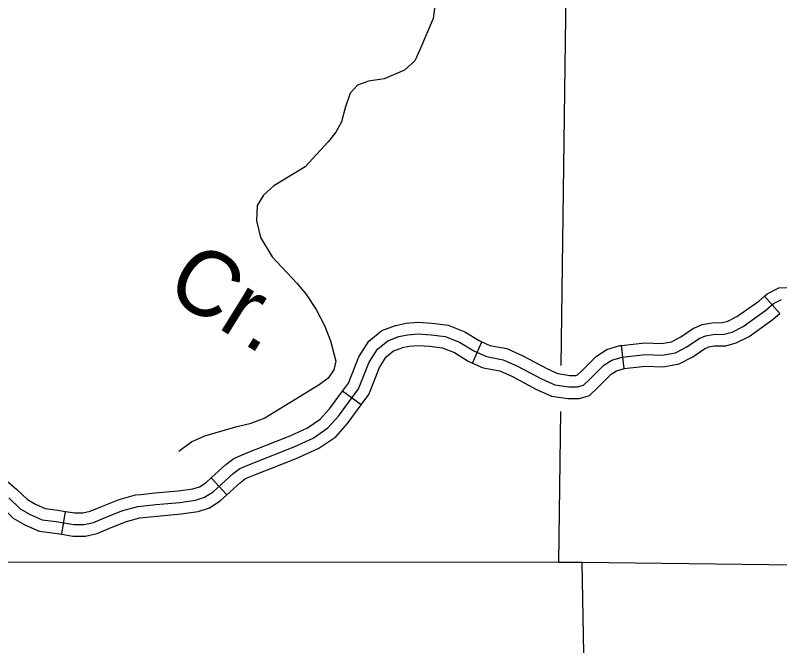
# Model space of a CAD drawing. Extents: x -19 to 366, y -4 to 359.
# Drawn here: x 136.698 to 137.635, y 197.944 to 198.716 of the extents above; entities that cross this region are included whole.
import ezdxf

# ---------------------------------------------------------------- set-up
doc = ezdxf.new("R2010")
doc.units = 0
for name, color, linetype in [('R_Axis', 7, 'Continuous'), ('R_Axis Annot', 7, 'Continuous'), ('R_Temp Easement', 7, 'Continuous'), ('Sheet Fence', 7, 'Continuous'), ('T_Indications', 7, 'Continuous')]:
    doc.layers.add(name, color=color, linetype=linetype)

msp = doc.modelspace()

# ---------------------------------------------------------------- linework, layer by layer
at = {"layer": 'R_Axis'}
msp.add_lwpolyline([(139.23142, 198.03736), (138.38944, 198.03328), (138.3734, 198.03349), (137.39231, 198.04601), (137.36365, 198.04602), (136.38943, 198.0464), (136.3709, 198.0464), (135.39084, 198.04643), (135.3637, 198.04701), (134.46147, 198.06627), (134.41844, 198.06697), (133.46736, 198.08257)], dxfattribs=at)
at = {"layer": 'R_Axis Annot'}
for points in [[(137.36682, 198.28741), (137.37684, 199.05047)], [(137.36365, 198.04602), (137.36607, 198.23073)], [(137.40599, 197.31164), (137.39231, 198.04601)]]:
    msp.add_lwpolyline(points, dxfattribs=at)
at = {"layer": 'R_Temp Easement'}
for points in [[(137.21218, 198.73082), (137.20961, 198.7126), (137.19351, 198.67384), (137.18714, 198.66054), (137.17471, 198.64911), (137.1498, 198.63839), (137.13053, 198.63566), (137.11694, 198.63068), (137.10791, 198.62078), (137.10193, 198.60293), (137.09747, 198.58584), (137.09033, 198.57329), (137.08093, 198.56112), (137.0527, 198.53066), (137.01461, 198.50737), (137.0018, 198.49594), (136.99392, 198.48339), (136.99324, 198.46442), (136.99824, 198.44395), (137.01233, 198.42049), (137.04272, 198.38798), (137.04854, 198.38124)], [(137.04854, 198.38124), (137.05375, 198.37521), (137.06631, 198.35591), (137.0766, 198.33623), (137.08386, 198.31729), (137.0904, 198.29265), (137.08817, 198.28202), (137.08103, 198.27175), (137.0701, 198.26336), (137.00334, 198.22289), (136.98523, 198.21562), (136.96747, 198.21175), (136.92933, 198.20061), (136.91385, 198.19372), (136.89802, 198.1819)]]:
    msp.add_lwpolyline(points, dxfattribs=at)
at = {"layer": 'Sheet Fence'}
for points in [[(139.44064, 1.53154), (139.25106, 10.14733), (139.06082, 18.76327), (138.86992, 27.37935), (138.67836, 35.99557), (138.48613, 44.61194), (138.29325, 53.22845), (138.09971, 61.84511), (137.9055, 70.46191), (137.71065, 79.07885), (137.51513, 87.69595), (137.31896, 96.31318), (137.12214, 104.93057), (136.92466, 113.54809), (136.72653, 122.16577), (136.52775, 130.78359), (136.32832, 139.40156), (136.12824, 148.01968), (135.9275, 156.63794), (135.72612, 165.25636), (135.5241, 173.87492), (135.32143, 182.49362), (135.11811, 191.11248), (134.91415, 199.73149), (134.70954, 208.35064), (134.50429, 216.96995), (134.2984, 225.5894), (134.09187, 234.209), (133.8847, 242.82876), (133.6769, 251.44866), (133.46845, 260.06872), (133.25937, 268.68892), (133.04965, 277.30928), (132.8393, 285.92978), (132.62831, 294.55044), (132.41669, 303.17125), (132.20444, 311.79221), (131.99156, 320.41333), (131.77805, 329.0346), (131.56391, 337.65601), (131.34914, 346.27759)], [(0, 198.13258), (7.10141, 198.13701), (14.2028, 198.15029), (21.30418, 198.17244), (28.40552, 198.20345), (35.50682, 198.24331), (42.60806, 198.29203), (49.70923, 198.34961), (56.81033, 198.41605), (63.91134, 198.49135), (71.01225, 198.5755), (78.11305, 198.66852), (85.21373, 198.77039), (92.31428, 198.88112), (99.41468, 199.0007), (106.51492, 199.12915), (113.61501, 199.26645), (120.71491, 199.4126), (127.81463, 199.56762), (134.91415, 199.73149), (142.01345, 199.90421), (149.11254, 200.0858), (156.2114, 200.27623), (163.31001, 200.47553), (170.40837, 200.68367), (177.50646, 200.90068), (184.60427, 201.12653), (191.7018, 201.36125), (198.79903, 201.60481), (205.89596, 201.85723), (212.99256, 202.1185), (220.08883, 202.38862), (227.18475, 202.6676), (234.28033, 202.95542), (241.37554, 203.2521), (248.47037, 203.55763), (255.56482, 203.87201), (262.65887, 204.19524), (269.75251, 204.52732), (276.84573, 204.86824), (283.93852, 205.21802), (291.03086, 205.57664), (298.12276, 205.94411), (305.21419, 206.32042), (312.30515, 206.70559), (319.39562, 207.09959), (326.48559, 207.50244), (333.57505, 207.91414), (340.664, 208.33468)], [(0, 189.51617), (7.11214, 189.52059), (14.22427, 189.53386), (21.33637, 189.55597), (28.44845, 189.58693), (35.56048, 189.62672), (42.67245, 189.67537), (49.78436, 189.73285), (56.89619, 189.79918), (64.00793, 189.87436), (71.11958, 189.95838), (78.23111, 190.05124), (85.34253, 190.15294), (92.45381, 190.26349), (99.56495, 190.38288), (106.67593, 190.51112), (113.78675, 190.6482), (120.89739, 190.79412), (128.00785, 190.94888), (135.11811, 191.11248), (142.22816, 191.28493), (149.33799, 191.46621), (156.44759, 191.65634), (163.55694, 191.85531), (170.66605, 192.06312), (177.77489, 192.27977), (184.88345, 192.50526), (191.99173, 192.73959), (199.09971, 192.98276), (206.20739, 193.23477), (213.31474, 193.49561), (220.42177, 193.7653), (227.52845, 194.04382), (234.63479, 194.33118), (241.74076, 194.62738), (248.84635, 194.93241), (255.95157, 195.24628), (263.05638, 195.56898), (270.16079, 195.90052), (277.26478, 196.24089), (284.36834, 196.5901), (291.47147, 196.94814), (298.57414, 197.31501), (305.67635, 197.69072), (312.77809, 198.07525), (319.87934, 198.46862), (326.9801, 198.87082), (334.08035, 199.28185), (341.18009, 199.7017)]]:
    msp.add_spline(points, degree=3, dxfattribs=at)
at = {"layer": 'T_Indications'}
for p, q in [((137.63452, 198.35085), (137.61596, 198.37237)), ((137.25804, 198.29018), (137.26943, 198.3162)), ((137.44394, 198.28355), (137.44069, 198.31177)), ((137.12157, 198.23903), (137.09871, 198.25589)), ((136.95688, 198.12858), (136.93779, 198.14962)), ((136.75448, 198.08047), (136.75916, 198.1085))]:
    msp.add_line(p, q, dxfattribs=at)
for points in [[(137.61596, 198.37237), (137.61916, 198.37512), (137.63333, 198.38221), (137.64843, 198.38268), (137.66501, 198.3796), (137.6875, 198.37185), (137.70535, 198.36051), (137.7137, 198.3562), (137.72131, 198.35398)], [(137.42858, 198.29395), (137.44132, 198.29755), (137.46972, 198.30081), (137.49062, 198.29983), (137.50662, 198.30277), (137.52066, 198.30996), (137.53568, 198.32041), (137.54351, 198.32368), (137.55298, 198.32532), (137.56637, 198.32564), (137.57616, 198.32826), (137.58955, 198.33512), (137.61763, 198.35504), (137.6271, 198.36321), (137.63689, 198.36811)], [(137.53127, 198.33397), (137.53952, 198.33741), (137.55159, 198.33949), (137.56433, 198.3398), (137.57103, 198.34159), (137.58216, 198.34729), (137.60886, 198.36624), (137.61596, 198.37237)], [(137.54221, 198.30775), (137.5475, 198.30996), (137.55437, 198.31114), (137.5684, 198.31148), (137.58129, 198.31492), (137.59694, 198.32294), (137.6264, 198.34385), (137.63452, 198.35085)], [(137.1659, 198.33685), (137.17611, 198.33908), (137.19147, 198.34021), (137.20859, 198.33913), (137.22808, 198.33656), (137.24854, 198.3286), (137.26609, 198.31766), (137.26943, 198.3162)], [(137.09871, 198.25589), (137.10589, 198.26564), (137.11876, 198.29783), (137.13082, 198.31689), (137.14679, 198.32993), (137.16364, 198.33635), (137.1659, 198.33685)], [(137.44069, 198.31177), (137.46924, 198.31506), (137.48966, 198.3141), (137.502, 198.31637), (137.51333, 198.32217), (137.52881, 198.33294), (137.53128, 198.33397)], [(136.68971, 198.12506), (136.70375, 198.11166), (136.71583, 198.10448), (136.73053, 198.09794), (136.74783, 198.09598), (136.76938, 198.09239), (136.78211, 198.09239), (136.79354, 198.095), (136.80987, 198.10186), (136.82946, 198.10938), (136.84774, 198.1146), (136.86994, 198.11689), (136.89933, 198.1195), (136.91859, 198.12212), (136.92936, 198.12571), (136.94014, 198.13257), (136.96463, 198.15479), (136.97279, 198.16099), (136.98683, 198.16687), (137.04005, 198.18811), (137.06258, 198.19824), (137.08086, 198.21065), (137.09359, 198.22502), (137.11841, 198.25867), (137.13147, 198.29134), (137.14159, 198.30735), (137.154, 198.31747), (137.16771, 198.3227), (137.17816, 198.32499), (137.19154, 198.32597), (137.20722, 198.32499), (137.22452, 198.3227), (137.24215, 198.31584), (137.25946, 198.30506), (137.27513, 198.2982), (137.2957, 198.29428), (137.31333, 198.28644), (137.34271, 198.27076), (137.35871, 198.26357), (137.37602, 198.26096), (137.38679, 198.26096), (137.39397, 198.26325), (137.40148, 198.27011), (137.41912, 198.28775), (137.42858, 198.29395)], [(137.17197, 198.30909), (137.18021, 198.3109), (137.19162, 198.31173), (137.20584, 198.31084), (137.22096, 198.30884), (137.23577, 198.30308), (137.25282, 198.29246), (137.25804, 198.29018)], [(137.26943, 198.3162), (137.27936, 198.31185), (137.29997, 198.30793), (137.31957, 198.29921), (137.34898, 198.28352), (137.36132, 198.27797)], [(137.36132, 198.27797), (137.36276, 198.27733), (137.37708, 198.27516), (137.38459, 198.27516), (137.3867, 198.27583), (137.39167, 198.28038), (137.4101, 198.29882), (137.42262, 198.30703), (137.43856, 198.31153), (137.44069, 198.31177)], [(137.12157, 198.23903), (137.13092, 198.25171), (137.14417, 198.28485), (137.15236, 198.2978), (137.1612, 198.30502), (137.17178, 198.30905), (137.17197, 198.30909)], [(137.44394, 198.28355), (137.4702, 198.28657), (137.49158, 198.28557), (137.51123, 198.28918), (137.52798, 198.29775), (137.54254, 198.30789), (137.54221, 198.30775)], [(137.25804, 198.29018), (137.2709, 198.28455), (137.29143, 198.28063), (137.30709, 198.27367), (137.33645, 198.258), (137.34968, 198.25206)], [(137.34968, 198.25206), (137.35467, 198.24982), (137.37495, 198.24675), (137.389, 198.24675), (137.40125, 198.25066), (137.4113, 198.25984), (137.42813, 198.27667), (137.43454, 198.28088), (137.44408, 198.28357), (137.44394, 198.28355)], [(137.0291, 198.19903), (137.0345, 198.20119), (137.05562, 198.21068), (137.07141, 198.2214), (137.08254, 198.23397), (137.09871, 198.25589)], [(137.03962, 198.17265), (137.04559, 198.17503), (137.06953, 198.18579), (137.09031, 198.1999), (137.10465, 198.21608), (137.12157, 198.23903)], [(136.93779, 198.14962), (136.95554, 198.16572), (136.96563, 198.1734), (136.98145, 198.18002), (137.0291, 198.19903)], [(136.95688, 198.12858), (136.97371, 198.14385), (136.97995, 198.14859), (136.9922, 198.15373), (137.03962, 198.17265)], [(136.67577, 198.1516), (136.68483, 198.14775), (136.6992, 198.13564), (136.7124, 198.12305), (136.72237, 198.11711), (136.7343, 198.11181), (136.7498, 198.11006), (136.75916, 198.1085)], [(136.85136, 198.12926), (136.86858, 198.13103), (136.89774, 198.13362), (136.91536, 198.13601), (136.92321, 198.13863), (136.93149, 198.1439), (136.93779, 198.14962)], [(136.66466, 198.12546), (136.66978, 198.12327), (136.68022, 198.11448), (136.69511, 198.10028), (136.70929, 198.09184), (136.72675, 198.08408), (136.74586, 198.08191), (136.75448, 198.08047)], [(136.75916, 198.1085), (136.77056, 198.10659), (136.78051, 198.10659), (136.78917, 198.10858), (136.80457, 198.11505), (136.82495, 198.12286), (136.84504, 198.12861), (136.85136, 198.12926)], [(136.85427, 198.101), (136.8713, 198.10275), (136.90091, 198.10538), (136.92182, 198.10822), (136.93552, 198.11279), (136.94879, 198.12124), (136.95688, 198.12858)], [(136.75448, 198.08047), (136.7682, 198.07819), (136.78372, 198.07819), (136.79791, 198.08143), (136.81516, 198.08868), (136.83396, 198.09589), (136.85044, 198.1006), (136.85427, 198.101)]]:
    msp.add_lwpolyline(points, dxfattribs=at)

# ---------------------------------------------------------------- texts
at = {"layer": 'R_Temp Easement'}
msp.add_text('Cr.', height=0.08, rotation=328.16514, dxfattribs=at).set_placement((136.87852, 198.37502))

doc.saveas('drawing.dxf')
